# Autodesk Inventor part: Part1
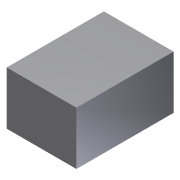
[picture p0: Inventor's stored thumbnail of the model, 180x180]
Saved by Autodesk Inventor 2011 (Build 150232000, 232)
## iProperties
Created: 2010-02
Part Number: Part1
Document SubType Name: Modeling
Designer: PN
Density: 1 g/cm^3
Author: PN
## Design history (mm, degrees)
sketch "Sketch1"
  geometry: L1 (-28.087, 18.826)-(-9.867, 18.826); L2 (-9.867, 18.826)-(-9.867, 4.964); L3 (-9.867, 4.964)-(-28.087, 4.964); L4 (-28.087, 4.964)-(-28.087, 18.826); 1 further point
  constraints: 8 end point, 2 parallel, 1 horizontal, 1 perpendicular
extrude "Extrusion1" new body sketch "Sketch1" distance "d0" = 25.4; taper "d1" = 0 deg
body "Solid1"
